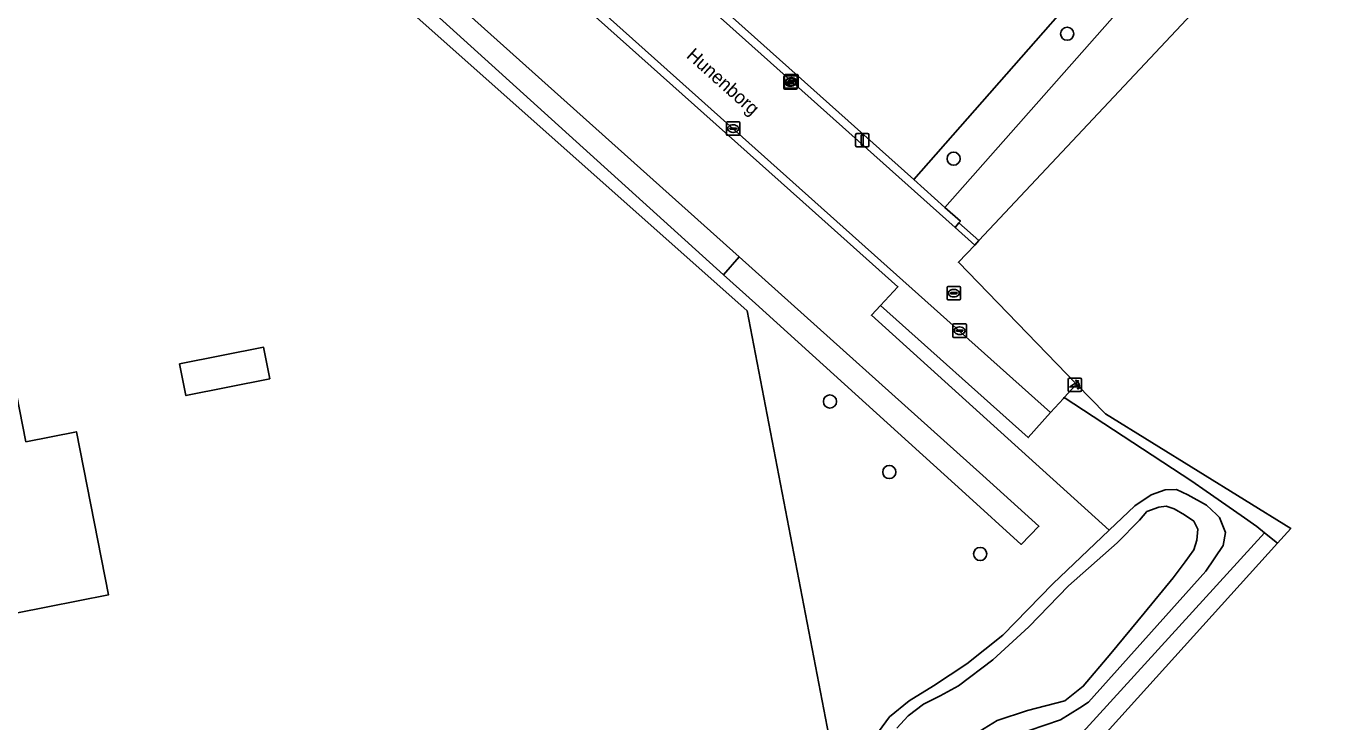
# Model space of a CAD drawing. Extents: x 157648 to 158502, y 379212 to 380938.
# Drawn here: x 158375.9 to 158472.9, y 380191.3 to 380243 of the extents above; entities that cross this region are included whole.
import ezdxf

# ---------------------------------------------------------------- set-up
doc = ezdxf.new("R2010")
doc.units = 0
for name, color, linetype in [('IMGEO_Boom', 7, 'Continuous'), ('IMGEO_Erf', 7, 'Continuous'), ('IMGEO_Fietspad_gesloten', 7, 'Continuous'), ('IMGEO_Groenvoorziening', 7, 'Continuous'), ('IMGEO_Kolk', 7, 'Continuous'), ('IMGEO_Lichtmast', 7, 'Continuous'), ('IMGEO_Oever', 7, 'Continuous'), ('IMGEO_Openbare_ruimte_label', 7, 'Continuous'), ('IMGEO_Pand', 7, 'Continuous'), ('IMGEO_Poller', 7, 'Continuous'), ('IMGEO_Rijbaan_lokaal_halfverhard', 7, 'Continuous'), ('IMGEO_Rijbaan_lokaal_open', 7, 'Continuous'), ('IMGEO_Rioolput', 7, 'Continuous'), ('IMGEO_Voetpad_halfverhard', 7, 'Continuous'), ('IMGEO_Voetpad_open', 7, 'Continuous'), ('IMGEO_Waterloop', 7, 'Continuous')]:
    doc.layers.add(name, color=color, linetype=linetype)

msp = doc.modelspace()

# ---------------------------------------------------------------- linework, layer by layer
at = {"layer": 'IMGEO_Boom'}
for centre in [(158453.211, 380242.403), (158444.777, 380233.119), (158435.591, 380215.073), (158439.996, 380209.829), (158446.751, 380203.741)]:
    msp.add_circle(centre, 0.489, dxfattribs=at)
at = {"layer": 'IMGEO_Erf'}
for points in [[(158385.44, 380281.833), (158396.328, 380272.254), (158441.82, 380231.568), (158462.293, 380254.879), (158454.886, 380261.5), (158454.843, 380261.446), (158407.523, 380303.702)], [(158429.436, 380221.799), (158397.765, 380250), (158373.398, 380271.696), (158349.129, 380244.613)], [(158339.86, 380155.207), (158339.295, 380140.154), (158336.963, 380139.709), (158336.936, 380139.824), (158330.828, 380138.619), (158330.845, 380138.521), (158319.174, 380136.236), (158318.727, 380136.148), (158318.621, 380135.936), (158302.772, 380121.88), (158310.837, 380105), (158320.267, 380086.067), (158350.695, 380093.122), (158360.95, 380104.759), (158436.002, 380187.68), (158429.436, 380221.799)]]:
    msp.add_lwpolyline(points, dxfattribs=at)
for points in [[(158393.991, 380216.745), (158387.751, 380215.514), (158387.287, 380217.87), (158393.527, 380219.1)], [(158379.624, 380212.821), (158382.012, 380200.707), (158377.506, 380199.818), (158372.6, 380198.852), (158372.141, 380201.181), (158365.894, 380199.951), (158363.269, 380213.275), (158368.175, 380214.242), (158375.166, 380215.619), (158375.864, 380212.08)]]:
    msp.add_lwpolyline(points, close=True, dxfattribs=at)
at = {"layer": 'IMGEO_Fietspad_gesloten'}
msp.add_lwpolyline([(158468.823, 380204.538), (158469.815, 380205.637), (158456.048, 380214.166), (158453.912, 380216.368), (158453.912, 380216.368), (158452.988, 380215.361), (158462.477, 380209.14), (158463.523, 380208.414), (158466.142, 380206.595), (158467.298, 380205.792), (158467.874, 380205.318)], close=True, dxfattribs=at)
at = {"layer": 'IMGEO_Groenvoorziening'}
for points in [[(158375.706, 380274.271), (158373.398, 380271.696), (158397.765, 380250), (158429.436, 380221.799), (158436.002, 380187.68), (158436.233, 380185.777), (158438.317, 380188.813), (158439.195, 380190.512), (158440.016, 380191.646), (158441.461, 380192.835), (158443.274, 380193.94), (158445.767, 380195.583), (158448.43, 380197.708), (158452.141, 380201.532), (158456.322, 380205.499), (158438.668, 380221.481), (158439.348, 380222.215), (158440.634, 380223.603), (158433.567, 380229.917), (158384.385, 380273.86)], [(158401.892, 380250), (158428.835, 380225.823), (158446.956, 380209.562), (158451.105, 380205.803), (158449.804, 380204.453), (158445.655, 380208.212), (158430.057, 380222.344), (158427.682, 380224.496), (158399.532, 380250)], [(158452.988, 380215.361), (158452.925, 380215.292), (158451.982, 380214.262), (158450.324, 380212.391), (158439.348, 380222.215), (158438.668, 380221.481), (158456.322, 380205.499), (158458.232, 380207.311), (158459.45, 380208.133), (158460.498, 380208.501), (158461.319, 380208.529), (158462.169, 380208.133), (158463.557, 380207.368), (158464.29, 380206.678), (158464.52, 380206.461), (158464.974, 380205.328), (158464.804, 380204.365), (158463.501, 380202.467), (158454.804, 380192.722), (158454.15, 380192.315), (158452.707, 380191.419), (158450.385, 380190.626)], [(158306.701, 380030.411), (158324.122, 380048.333), (158334.417, 380059.036), (158343.864, 380068.969), (158356.557, 380083.229), (158374.632, 380103.233), (158398.889, 380128.586), (158419.7, 380151.493), (158441.375, 380176.227), (158467.874, 380205.318), (158467.298, 380205.792), (158466.142, 380206.595), (158463.523, 380208.414), (158462.477, 380209.14), (158452.988, 380215.361)]]:
    msp.add_lwpolyline(points, dxfattribs=at)
msp.add_lwpolyline([(158444.13, 380229.501), (158462.228, 380250), (158464.548, 380252.628), (158462.293, 380254.879), (158441.82, 380231.568)], close=True, dxfattribs=at)
at = {"layer": 'IMGEO_Kolk'}
for p, q in [((158432.156, 380238.354), (158432.156, 380239.206)), ((158432.221, 380238.438), (158432.221, 380239.29)), ((158432.231, 380239.28), (158433.083, 380239.28)), ((158432.296, 380239.364), (158433.148, 380239.364)), ((158432.709, 380239.144), (158432.734, 380239.144)), ((158433.157, 380239.206), (158433.157, 380238.354)), ((158433.222, 380239.29), (158433.222, 380238.438)), ((158433.083, 380238.28), (158432.231, 380238.28)), ((158433.148, 380238.364), (158432.296, 380238.364)), ((158432.415, 380238.774), (158432.415, 380238.786)), ((158432.853, 380238.737), (158432.455, 380238.737)), ((158432.458, 380238.823), (158432.856, 380238.823)), ((158432.48, 380238.858), (158432.48, 380238.87)), ((158432.918, 380238.821), (158432.52, 380238.821)), ((158432.523, 380238.907), (158432.921, 380238.907)), ((158432.667, 380238.5), (158432.642, 380238.5)), ((158432.644, 380239.06), (158432.669, 380239.06)), ((158432.732, 380238.584), (158432.707, 380238.584)), ((158432.899, 380238.786), (158432.899, 380238.774)), ((158432.964, 380238.87), (158432.964, 380238.858)), ((158427.902, 380234.929), (158427.902, 380235.781)), ((158427.977, 380235.855), (158428.829, 380235.855)), ((158428.161, 380235.349), (158428.161, 380235.361)), ((158428.599, 380235.312), (158428.201, 380235.312)), ((158428.204, 380235.398), (158428.602, 380235.398)), ((158428.39, 380235.635), (158428.415, 380235.635)), ((158428.645, 380235.361), (158428.645, 380235.349)), ((158428.903, 380235.781), (158428.903, 380234.929)), ((158428.829, 380234.855), (158427.977, 380234.855)), ((158428.413, 380235.075), (158428.388, 380235.075)), ((158444.718, 380219.906), (158444.718, 380220.758)), ((158444.793, 380220.832), (158445.645, 380220.832)), ((158445.719, 380220.758), (158445.719, 380219.906)), ((158445.645, 380219.832), (158444.793, 380219.832)), ((158444.977, 380220.326), (158444.977, 380220.338)), ((158445.415, 380220.289), (158445.017, 380220.289)), ((158445.02, 380220.375), (158445.418, 380220.375)), ((158445.229, 380220.052), (158445.204, 380220.052)), ((158445.206, 380220.612), (158445.231, 380220.612)), ((158445.461, 380220.338), (158445.461, 380220.326))]:
    msp.add_line(p, q, dxfattribs=at)
for points in [[(158432.156, 380238.354), (158432.156, 380239.206)], [(158432.221, 380238.438), (158432.221, 380239.29)], [(158432.231, 380239.28), (158433.083, 380239.28)], [(158432.296, 380239.364), (158433.148, 380239.364)], [(158433.157, 380239.206), (158433.157, 380238.354)], [(158433.222, 380239.29), (158433.222, 380238.438)], [(158433.083, 380238.28), (158432.231, 380238.28)], [(158433.148, 380238.364), (158432.296, 380238.364)], [(158427.902, 380234.929), (158427.902, 380235.781)], [(158427.977, 380235.855), (158428.829, 380235.855)], [(158428.903, 380235.781), (158428.903, 380234.929)], [(158428.829, 380234.855), (158427.977, 380234.855)], [(158444.718, 380219.906), (158444.718, 380220.758)], [(158444.793, 380220.832), (158445.645, 380220.832)], [(158445.719, 380220.758), (158445.719, 380219.906)], [(158445.645, 380219.832), (158444.793, 380219.832)]]:
    msp.add_lwpolyline(points, dxfattribs=at)
for centre, radius, start, end in [((158432.233, 380239.204), 0.0765, 91.55205, 178.44795), ((158432.233, 380239.204), 0.0765, 91.55205, 178.44795), ((158432.298, 380239.288), 0.0765, 91.55205, 178.44795), ((158432.298, 380239.288), 0.0765, 91.55205, 178.44795), ((158433.081, 380239.204), 0.0765, 1.55205, 88.44795), ((158433.081, 380239.204), 0.0765, 1.55205, 88.44795), ((158433.146, 380239.288), 0.0765, 1.55205, 88.44795), ((158433.146, 380239.288), 0.0765, 1.55205, 88.44795), ((158432.233, 380238.356), 0.0765, 181.55205, 268.44795), ((158432.233, 380238.356), 0.0765, 181.55205, 268.44795), ((158432.298, 380238.44), 0.0765, 181.55205, 268.44795), ((158432.298, 380238.44), 0.0765, 181.55205, 268.44795), ((158432.455, 380238.783), 0.0403, 85.87752, 175.75265), ((158432.452, 380238.773), 0.0366, 178.93798, 274.71019), ((158432.52, 380238.867), 0.0403, 85.87752, 175.75265), ((158432.517, 380238.857), 0.0366, 178.93798, 274.71019), ((158432.856, 380238.78), 0.043, 264.86636, 352.45326), ((158432.86, 380238.785), 0.0386, 1.73085, 96.63898), ((158432.921, 380238.864), 0.043, 264.86636, 352.45326), ((158432.925, 380238.869), 0.0386, 1.73085, 96.63898), ((158433.081, 380238.356), 0.0765, 271.55205, 358.44795), ((158433.081, 380238.356), 0.0765, 271.55205, 358.44795), ((158433.146, 380238.44), 0.0765, 271.55205, 358.44795), ((158433.146, 380238.44), 0.0765, 271.55205, 358.44795), ((158427.979, 380235.779), 0.0765, 91.55205, 178.44795), ((158427.979, 380235.779), 0.0765, 91.55205, 178.44795), ((158428.201, 380235.358), 0.0403, 85.87752, 175.75265), ((158428.198, 380235.348), 0.0366, 178.93798, 274.71019), ((158428.602, 380235.355), 0.043, 264.86636, 352.45326), ((158428.606, 380235.36), 0.0386, 1.73085, 96.63898), ((158428.827, 380235.779), 0.0765, 1.55205, 88.44795), ((158428.827, 380235.779), 0.0765, 1.55205, 88.44795), ((158427.979, 380234.931), 0.0765, 181.55205, 268.44795), ((158427.979, 380234.931), 0.0765, 181.55205, 268.44795), ((158428.827, 380234.931), 0.0765, 271.55205, 358.44795), ((158428.827, 380234.931), 0.0765, 271.55205, 358.44795), ((158444.795, 380220.756), 0.0765, 91.55205, 178.44795), ((158444.795, 380220.756), 0.0765, 91.55205, 178.44795), ((158445.643, 380220.756), 0.0765, 1.55205, 88.44795), ((158445.643, 380220.756), 0.0765, 1.55205, 88.44795), ((158444.795, 380219.908), 0.0765, 181.55205, 268.44795), ((158444.795, 380219.908), 0.0765, 181.55205, 268.44795), ((158445.017, 380220.335), 0.0403, 85.87752, 175.75265), ((158445.014, 380220.325), 0.0366, 178.93798, 274.71019), ((158445.418, 380220.332), 0.043, 264.86636, 352.45326), ((158445.422, 380220.337), 0.0386, 1.73085, 96.63898), ((158445.643, 380219.908), 0.0765, 271.55205, 358.44795), ((158445.643, 380219.908), 0.0765, 271.55205, 358.44795)]:
    msp.add_arc(centre, radius, start, end, dxfattribs=at)
for centre, major_axis, ratio, start_param, end_param in [((158432.708, 380238.864), (-0.387, 0.002), 0.722429, 4.712389, 7.853982), ((158432.733, 380238.864), (-0.39, 0.002), 0.717154, 1.570796, 4.712389), ((158432.643, 380238.78), (-0.387, 0.002), 0.722429, 4.712389, 7.853982), ((158432.668, 380238.78), (-0.39, 0.002), 0.717154, 1.570796, 4.712389), ((158428.389, 380235.355), (-0.387, 0.002), 0.722429, 4.712389, 7.853982), ((158428.414, 380235.355), (-0.39, 0.002), 0.717154, 1.570796, 4.712389), ((158445.205, 380220.332), (-0.387, 0.002), 0.722429, 4.712389, 7.853982), ((158445.23, 380220.332), (-0.39, 0.002), 0.717154, 1.570796, 4.712389)]:
    msp.add_ellipse(centre, major_axis=major_axis, ratio=ratio, start_param=start_param, end_param=end_param, dxfattribs=at)
at = {"layer": 'IMGEO_Lichtmast'}
for p, q in [((158437.497, 380234.1), (158437.497, 380234.9)), ((158437.497, 380234.9), (158437.497, 380234.1)), ((158437.597, 380235), (158438.387, 380235)), ((158438.387, 380235), (158437.597, 380235)), ((158438.487, 380234.9), (158438.487, 380234.1)), ((158438.487, 380234.1), (158438.487, 380234.9)), ((158438.387, 380234), (158437.597, 380234)), ((158437.597, 380234), (158438.387, 380234))]:
    msp.add_line(p, q, dxfattribs=at)
msp.add_lwpolyline([(158437.917, 380234.875), (158438.067, 380234.875), (158438.067, 380234.125), (158437.917, 380234.125), (158437.917, 380234.875)], dxfattribs=at)
for centre, start, end in [((158437.597, 380234.9), 90, 180), ((158437.597, 380234.9), 90, 180), ((158438.387, 380234.9), 0, 90), ((158438.387, 380234.9), 360, 90), ((158437.597, 380234.1), 180, 270), ((158437.597, 380234.1), 180, 270), ((158438.387, 380234.1), 270, 0), ((158438.387, 380234.1), 270, 0)]:
    msp.add_arc(centre, 0.1, start, end, dxfattribs=at)
at = {"layer": 'IMGEO_Oever'}
for points in [[(158450.385, 380190.626), (158452.707, 380191.419), (158454.15, 380192.315), (158454.804, 380192.722), (158463.501, 380202.467), (158464.804, 380204.365), (158464.974, 380205.328), (158464.52, 380206.461), (158464.29, 380206.678), (158463.557, 380207.368), (158462.169, 380208.133), (158461.319, 380208.529), (158460.498, 380208.501), (158459.45, 380208.133), (158458.232, 380207.311), (158456.322, 380205.499), (158452.141, 380201.532), (158448.43, 380197.708), (158445.767, 380195.583), (158443.274, 380193.94), (158441.461, 380192.835), (158440.016, 380191.646), (158439.195, 380190.512)], [(158440.555, 380190.796), (158441.405, 380191.702), (158442.538, 380192.58), (158443.784, 380193.204), (158445.144, 380193.94), (158447.693, 380195.866), (158450.356, 380198.331), (158453.302, 380201.362), (158456.928, 380204.563), (158458.571, 380206.263), (158459.138, 380206.886), (158460.016, 380207.226), (158460.554, 380207.283), (158461.149, 380207.084), (158461.914, 380206.66), (158462.622, 380206.178), (158462.906, 380205.583), (158462.849, 380204.762), (158462.622, 380204.053), (158461.971, 380203.147), (158461.093, 380201.957), (158458.94, 380199.351), (158456.447, 380196.348), (158454.407, 380193.912), (158453.047, 380192.835), (158450.271, 380192.099), (158448.005, 380191.362), (158445.116, 380189.578)]]:
    msp.add_lwpolyline(points, dxfattribs=at)
at = {"layer": 'IMGEO_Pand'}
for points in [[(158393.991, 380216.745), (158393.527, 380219.1), (158387.287, 380217.87), (158387.751, 380215.514)], [(158377.506, 380199.818), (158382.012, 380200.707), (158379.624, 380212.821), (158375.864, 380212.08), (158375.166, 380215.619), (158368.175, 380214.242), (158363.269, 380213.275), (158365.894, 380199.951), (158372.141, 380201.181), (158372.6, 380198.852)]]:
    msp.add_lwpolyline(points, close=True, dxfattribs=at)
at = {"layer": 'IMGEO_Poller'}
for p, q in [((158454.184, 380216.805), (158453.376, 380216.805)), ((158454.184, 380216.805), (158453.376, 380216.805)), ((158453.282, 380216.71), (158453.282, 380215.903)), ((158453.282, 380216.71), (158453.282, 380215.903)), ((158453.376, 380215.808), (158454.184, 380215.808)), ((158453.376, 380215.808), (158454.184, 380215.808)), ((158454.278, 380215.903), (158454.278, 380216.71)), ((158454.278, 380215.903), (158454.278, 380216.71))]:
    msp.add_line(p, q, dxfattribs=at)
for points in [[(158453.917, 380216.161), (158453.404, 380216.161), (158453.834, 380216.436)], [(158453.961, 380216.534), (158453.949, 380216.461), (158453.824, 380216.666)], [(158453.824, 380216.666), (158454.055, 380216.6), (158453.984, 380216.568)], [(158453.977, 380215.989), (158454.043, 380216.22), (158454.073, 380216.152)], [(158454.109, 380216.125), (158454.181, 380216.114), (158453.977, 380215.989)]]:
    msp.add_lwpolyline(points, dxfattribs=at)
for centre, radius, start, end in [((158453.376, 380216.71), 0.0946, 90, 180), ((158453.376, 380216.71), 0.0946, 90, 180), ((158454.184, 380216.71), 0.0946, 0, 90), ((158454.184, 380216.71), 0.0946, 0, 90), ((158453.376, 380215.903), 0.0946, 180, 270), ((158453.376, 380215.903), 0.0946, 180, 270), ((158453.589, 380216.211), 0.332, 351.32473, 42.4854), ((158453.603, 380216.221), 0.476, 351.75274, 41.16905), ((158453.603, 380216.221), 0.516, 349.35686, 42.29123), ((158454.184, 380215.903), 0.0946, 270, 0), ((158454.184, 380215.903), 0.0946, 270, 0)]:
    msp.add_arc(centre, radius, start, end, dxfattribs=at)
at = {"layer": 'IMGEO_Rijbaan_lokaal_halfverhard'}
msp.add_lwpolyline([(158446.652, 380227.03), (158472.871, 380254.972), (158470.631, 380256.956), (158469.362, 380258.081), (158466.558, 380254.905), (158464.022, 380256.796), (158462.293, 380254.879), (158464.548, 380252.628), (158462.228, 380250), (158444.13, 380229.501), (158445.278, 380228.475), (158445.173, 380228.353)], close=True, dxfattribs=at)
at = {"layer": 'IMGEO_Rijbaan_lokaal_open'}
for points in [[(158446.344, 380226.702), (158444.879, 380228.012), (158386.082, 380280.588)], [(158383.955, 380275.03), (158384.74, 380274.414), (158451.982, 380214.262), (158452.925, 380215.292), (158452.988, 380215.361), (158453.912, 380216.368), (158453.912, 380216.368), (158445.137, 380225.416), (158446.344, 380226.702)]]:
    msp.add_lwpolyline(points, dxfattribs=at)
at = {"layer": 'IMGEO_Rioolput'}
for p, q in [((158444.362, 380223.625), (158445.214, 380223.625)), ((158444.287, 380222.699), (158444.287, 380223.551)), ((158445.214, 380222.625), (158444.362, 380222.625)), ((158444.546, 380223.119), (158444.546, 380223.131)), ((158444.984, 380223.082), (158444.586, 380223.082)), ((158444.589, 380223.168), (158444.987, 380223.168)), ((158444.798, 380222.845), (158444.773, 380222.845)), ((158444.775, 380223.405), (158444.8, 380223.405)), ((158445.03, 380223.131), (158445.03, 380223.119)), ((158445.288, 380223.551), (158445.288, 380222.699))]:
    msp.add_line(p, q, dxfattribs=at)
for points in [[(158444.362, 380223.625), (158445.214, 380223.625)], [(158444.287, 380222.699), (158444.287, 380223.551)], [(158445.214, 380222.625), (158444.362, 380222.625)], [(158445.288, 380223.551), (158445.288, 380222.699)]]:
    msp.add_lwpolyline(points, dxfattribs=at)
for centre, radius, start, end in [((158444.364, 380223.549), 0.0765, 91.55205, 178.44795), ((158444.364, 380223.549), 0.0765, 91.55205, 178.44795), ((158445.212, 380223.549), 0.0765, 1.55205, 88.44795), ((158445.212, 380223.549), 0.0765, 1.55205, 88.44795), ((158444.364, 380222.701), 0.0765, 181.55205, 268.44795), ((158444.364, 380222.701), 0.0765, 181.55205, 268.44795), ((158444.586, 380223.128), 0.0403, 85.87752, 175.75265), ((158444.583, 380223.118), 0.0366, 178.93798, 274.71019), ((158444.987, 380223.125), 0.043, 264.86636, 352.45326), ((158444.991, 380223.13), 0.0386, 1.73085, 96.63898), ((158445.212, 380222.701), 0.0765, 271.55205, 358.44795), ((158445.212, 380222.701), 0.0765, 271.55205, 358.44795)]:
    msp.add_arc(centre, radius, start, end, dxfattribs=at)
for centre, major_axis, ratio, start_param, end_param in [((158444.774, 380223.125), (-0.387, 0.002), 0.722429, 4.712389, 7.853982), ((158444.799, 380223.125), (-0.39, 0.002), 0.717154, 1.570796, 4.712389)]:
    msp.add_ellipse(centre, major_axis=major_axis, ratio=ratio, start_param=start_param, end_param=end_param, dxfattribs=at)
at = {"layer": 'IMGEO_Voetpad_halfverhard'}
for points in [[(158468.823, 380204.538), (158467.874, 380205.318), (158441.375, 380176.227), (158419.7, 380151.493), (158398.889, 380128.586), (158374.632, 380103.233), (158356.557, 380083.229), (158343.864, 380068.969), (158334.417, 380059.036), (158324.122, 380048.333), (158306.701, 380030.411)], [(158308.359, 380028.676), (158325.744, 380046.609), (158336.215, 380057.388), (158345.664, 380067.502), (158358.23, 380081.535), (158376.274, 380101.52), (158400.569, 380126.856), (158421.483, 380149.885), (158443.13, 380174.684), (158443.87, 380175.489), (158443.189, 380176.129), (158468.823, 380204.538)]]:
    msp.add_lwpolyline(points, dxfattribs=at)
at = {"layer": 'IMGEO_Voetpad_open'}
msp.add_lwpolyline([(158386.082, 380280.588), (158444.879, 380228.012), (158445.173, 380228.353), (158445.278, 380228.475), (158444.13, 380229.501), (158441.82, 380231.568), (158396.328, 380272.254), (158385.44, 380281.833)], dxfattribs=at)
for points in [[(158384.74, 380274.414), (158383.955, 380275.03), (158383.552, 380274.605), (158384.385, 380273.86), (158433.567, 380229.917), (158440.634, 380223.603), (158439.348, 380222.215), (158450.324, 380212.391), (158451.982, 380214.262)], [(158446.652, 380227.03), (158445.173, 380228.353), (158444.879, 380228.012), (158446.344, 380226.702)]]:
    msp.add_lwpolyline(points, close=True, dxfattribs=at)
at = {"layer": 'IMGEO_Waterloop'}
for points in [[(158399.532, 380250), (158427.682, 380224.496), (158428.835, 380225.823), (158401.892, 380250)], [(158445.116, 380189.578), (158448.005, 380191.362), (158450.271, 380192.099), (158453.047, 380192.835), (158454.407, 380193.912), (158456.447, 380196.348), (158458.94, 380199.351), (158461.093, 380201.957), (158461.971, 380203.147), (158462.622, 380204.053), (158462.849, 380204.762), (158462.906, 380205.583), (158462.622, 380206.178), (158461.914, 380206.66), (158461.149, 380207.084), (158460.554, 380207.283), (158460.016, 380207.226), (158459.138, 380206.886), (158458.571, 380206.263), (158456.928, 380204.563), (158453.302, 380201.362), (158450.356, 380198.331), (158447.693, 380195.866), (158445.144, 380193.94), (158443.784, 380193.204), (158442.538, 380192.58), (158441.405, 380191.702), (158440.555, 380190.796)]]:
    msp.add_lwpolyline(points, dxfattribs=at)
msp.add_lwpolyline([(158428.835, 380225.823), (158427.682, 380224.496), (158430.057, 380222.344), (158445.655, 380208.212), (158449.804, 380204.453), (158451.105, 380205.803), (158446.956, 380209.562)], close=True, dxfattribs=at)

# ---------------------------------------------------------------- texts
at = {"layer": 'IMGEO_Openbare_ruimte_label'}
msp.add_text('Hunenborg', height=1, rotation=318.16185, dxfattribs=at).set_placement((158424.858, 380240.683))

doc.saveas('drawing.dxf')
